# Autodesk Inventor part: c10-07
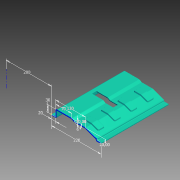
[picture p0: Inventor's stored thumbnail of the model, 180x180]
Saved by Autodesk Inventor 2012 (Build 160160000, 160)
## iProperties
Created: 2011-01
Part Number: c10-07
Material: Aluminum-6061
Document SubType Name: Sheet Metal
Designer: Beta-8540w
Density: 2.71 g/cm^3
Sheet Metal Rule: Aluminum - 3.4mm
Author: Beta-8540w
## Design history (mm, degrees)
sketch "Sketch1"
  geometry: L1 (0, 0)-(20, 0); L2 (20, 0)-(20, 30); L3 (20, 30)-(90, 30); L4 (100.392, 24)-(150, 24); L5 (150, 24)-(200, 5.801); L6 (200, 5.801)-(200, 0); L7 (200, 0)-(220, 0); L8 (-200, 0)-(-200, 73.265); L9 (90, 30)-(100.392, 24); 1 further point
  constraints: 18 end point, 3 collinear, 3 parallel, 2 perpendicular, 1 coincident, 1 horizontal, 1 horizontal alignment
  dimensions: "d5" = 20 distance of L1.start L1.end; "d6" = 30 distance of L1.end L2.end; "d7" = 70 distance of L2.end L3.end; "d9" = 220 distance of L7.end point (0, 0); "d11" = 20 deg angle of L5 L4; "d12" = 200 distance from line of point (0, 0) L8; "d13" = 6 vertical distance of L3.end L4.start; "d14" = 130 distance from line of L4.end L2; "d15" = 30 deg angle of L9 L3
node "Contour Flange1"
sketch "Sketch3" dims "d35" = 10
  geometry: L1 (-100.928, -300)-(-100.928, 0) reference; L2 (-100.928, 0)-(-82.928, 0) reference; 4 further points
  constraints: 1 vertical, 3 other
  dimensions: "d28" = 150 distance from line of point (49.072, -40) L1; "d29" = 40 distance from line of L2 point (49.072, -40); "d32" = 73 distance of point (49.072, -40) point (49.072, -113)
node "Unfold1"
feature "iFeature4:1"
node "Refold1"
sketch "Sketch4"
  geometry: L1 (14.6, -140)-(109.951, -140); L2 (109.951, -140)-(109.951, -160); L3 (109.951, -160)-(14.6, -160); L4 (14.6, -160)-(14.6, -140); L5 (-25.4, -300)-(-25.4, 0) reference; L6 (93.374, -103.348)-(93.374, -122.652) reference; L7 (124.951, -97.771)-(98.951, -97.771) reference; L8 (124.951, -55.229)-(124.951, -97.771) reference; L9 (98.951, -55.229)-(124.951, -55.229) reference; L10 (93.374, -30.348)-(93.374, -49.652) reference; L11 (124.951, -24.771)-(98.951, -24.771) reference; L12 (124.951, 0)-(124.951, -24.771) reference; L13 (76.831, 0)-(124.951, 0) reference; L14 (124.951, -300)-(76.831, -300) reference; L15 (124.951, -274.229)-(124.951, -300) reference; L16 (63.153, 0)-(63.153, -300) reference; L17 (64.984, 0)-(64.984, -300) reference; L18 (75.001, 0)-(75.001, -300) reference; L19 (76.831, 0)-(76.831, -300) reference; L20 (75.916, 0)-(75.916, -300) reference; L21 (124.951, -243.771)-(98.951, -243.771) reference; L22 (124.951, -201.229)-(124.951, -243.771) reference; L23 (64.984, -300)-(63.153, -300) reference; L24 (63.153, 0)-(64.984, 0) reference; L25 (63.153, -300)-(0, -300) reference; L26 (0, 0)-(0, -300) reference; L27 (0, 0)-(63.153, 0) reference; L28 (98.951, -201.229)-(124.951, -201.229) reference; L29 (64.984, 0)-(75.001, 0) reference; L30 (75.001, -300)-(64.984, -300) reference; L31 (75.001, 0)-(76.831, 0) reference; L32 (76.831, -300)-(75.001, -300) reference; L33 (98.951, -274.229)-(124.951, -274.229) reference; L34 (93.374, -249.348)-(93.374, -268.652) reference; L35 (93.374, -176.348)-(93.374, -195.652) reference; L36 (124.951, -170.771)-(98.951, -170.771) reference; L37 (124.951, -128.229)-(124.951, -170.771) reference; L38 (98.951, -128.229)-(124.951, -128.229) reference; L39 (64.068, -300)-(64.068, 0) reference; A1 r 5.577 centre (98.951, -103.348) between (98.951, -97.771) and (93.374, -103.348) reference; A2 r 5.577 centre (98.951, -49.652) between (93.374, -49.652) and (98.951, -55.229) reference; A3 r 5.577 centre (98.951, -30.348) between (98.951, -24.771) and (93.374, -30.348) reference; A4 r 5.577 centre (98.951, -195.652) between (93.374, -195.652) and (98.951, -201.229) reference; A5 r 5.577 centre (98.951, -268.652) between (93.374, -268.652) and (98.951, -274.229) reference; A6 r 5.577 centre (98.951, -249.348) between (98.951, -243.771) and (93.374, -249.348) reference; A7 r 5.577 centre (98.951, -176.348) between (98.951, -170.771) and (93.374, -176.348) reference; A8 r 5.577 centre (98.951, -122.652) between (93.374, -122.652) and (98.951, -128.229) reference; 2 further points
  constraints: 8 end point, 2 midpoint, 2 parallel, 1 horizontal, 1 horizontal alignment, 1 perpendicular
  dimensions: "d41" = 20 distance of L3.end L1.start; "d42" = 40 distance between parallel lines of L5 L4; "d43" = 15 distance between parallel lines of L37 L2
cut "Cut1" sketch "Sketch4" dims "d44" = 3.4 (= Thickness), "d45" = 0
body "Solid2"
face "Plate2" dims "d16" = 3.4 (= BendReliefWidth), "d17" = 1.7 (= BendReliefDepth), "d18" = 6.8 (= MinimumRemnant), "d19" = 2 (= BendRadius), "d20" = 300, "d21" = 2 (= BendRadius), "d22" = 3.4, "d23" = 13.6 (= CornerReliefSize), "d24" = 3.4 (= GapSize), "d25" = 2 (= JacobiRadiusSize), "SeamGap" = 0.01, "Thickness" = 3.4 (derived)
bend "Bend1" dims "d16" = 3.4 (= BendReliefWidth), "d17" = 1.7 (= BendReliefDepth), "d18" = 6.8 (= MinimumRemnant), "d19" = 2 (= BendRadius), "d21" = 2 (= BendRadius), "d22" = 3.4, "SeamGap" = 0.01, "Thickness" = 3.4 (derived)
feature "Corner1" dims "d22" = 3.4, "d23" = 13.6 (= CornerReliefSize), "d24" = 3.4 (= GapSize), "d25" = 2 (= JacobiRadiusSize)
other parameters: "BendRadius" = 2 (derived), "BendReliefWidth" = 3.4 (= Thickness), "BendReliefDepth" = 1.7 (= 0.5 x Thickness), "CornerReliefSize" = 13.6 (= 4 x Thickness), "MinimumRemnant" = 6.8 (= 2 x Thickness), "TransitionRadius" = 2 (= BendRadius), "JacobiRadiusSize" = 2 (= BendRadius), "GapSize" = 3.4 (= Thickness), "d4" = 2 (= BendRadius), "d40" = 0
